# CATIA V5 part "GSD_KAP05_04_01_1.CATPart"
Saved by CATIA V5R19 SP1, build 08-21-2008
Part number: GSD_KAP05_04_01
Definition: Beispielmodell: Linien erzeugen
Description: CATIA V5 Flächenmodellierung  Copyright (c) 2009 Maik Hertha IT Consultants
Bounding box of the stored display mesh (mm): x 0 to 50, y 0 to 50, z 0 to 50
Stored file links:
  \GSD_BUCH_UEBUNG\GSD_KAP05_04_01_1.CATPart
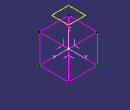
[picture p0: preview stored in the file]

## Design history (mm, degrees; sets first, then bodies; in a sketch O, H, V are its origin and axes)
AxisSystem1: origin (0, 0, 0), X (1, 0, 0), Y (0, 1, 0), Z (0, 0, 1)
Set1
  Point1: (0, 0, 0), in AxisSystem1
  Point2: (50, 0, 0), relative to Point1, in AxisSystem1
  Point3: (0, 50, 0), relative to Point2, in AxisSystem1
  Point4: (-50, 0, 0), relative to Point3, in AxisSystem1
  Plane1: type Equation, A 0, B 0, C 1, RefAxis AxisSystem1, Length 50
  Line1: type PtDir, LineFirstUpto Point1, LineSecondUpto Plane1, Direction Plane1, Start 0, End 20
  Line2: type PtDir, LineFirstUpto Point2, LineSecondUpto Plane1, Direction Plane1, Start 0, End 20
  Line3: type PtDir, LineFirstUpto Point3, LineSecondUpto Plane1, Direction Plane1, Start 0, End 20
  Line4: type PtDir, LineFirstUpto Point4, LineSecondUpto Plane1, Direction Plane1, Start 0, End 20
  Line5: type PtPt, SecondPoint Point3, FirstPoint Point2
  Line6: type PtPt, SecondPoint Point4, FirstPoint Point3
  Line7: type PtPt, SecondPoint Point1, FirstPoint Point4
  Line8: type PtPt, SecondPoint Point2, FirstPoint Point1
  Line9: type PtPt, SecondPoint {point type OnCurve, Support Line3, Ratio 1}, FirstPoint {point type OnCurve, Support Line2, Ratio 1}
  Line10: type PtPt, SecondPoint {point type OnCurve, Support Line4, Ratio 1}, FirstPoint {point type OnCurve, Support Line3, Ratio 1}
  Line11: type PtPt, SecondPoint {point type OnCurve, Support Line1, Ratio 1}, FirstPoint {point type OnCurve, Support Line4, Ratio 1}
  Line12: type PtPt, SecondPoint {point type OnCurve, Support Line2, Ratio 1}, FirstPoint {point type OnCurve, Support Line1, Ratio 1}
Body1 (main body)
